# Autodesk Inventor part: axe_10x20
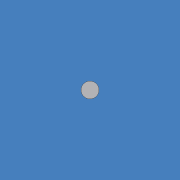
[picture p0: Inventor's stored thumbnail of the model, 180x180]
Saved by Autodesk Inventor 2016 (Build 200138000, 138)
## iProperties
Shininess: 64.0
Length Units: 11269
Angle Units: 11279
Time Units: 11290
Mass Units: 11283
Length Display Precision: 3
Angle Display Precision: 2
Compacted: True
Part Number: axe_10x20
Document SubType Name: Modeling
Created: 2003-07
Material: Générique
Designer: trameau
Density: 1 g/cm^3
Appearance: Par défaut
Density: 0.0
Volumn: 0.0
Area: 0.0
PropertySet Name: Model Information
Control State: 0
Master: False
Checked Out: False
Author: trameau
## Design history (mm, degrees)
sketch "Esquisse1"
  geometry: C1 r 5 at (0, 0)
  constraints: 1 centre point
  dimensions: "d0" = 10 dimension on C1.centre C1; "d0" = 10 diameter of C1
extrude "Extrusion1" new body sketch "Esquisse1" distance "d1" = 20; taper "d2" = 0 deg
node "Solide1"
node "Corps solides"
node "Corps surfaciques"
